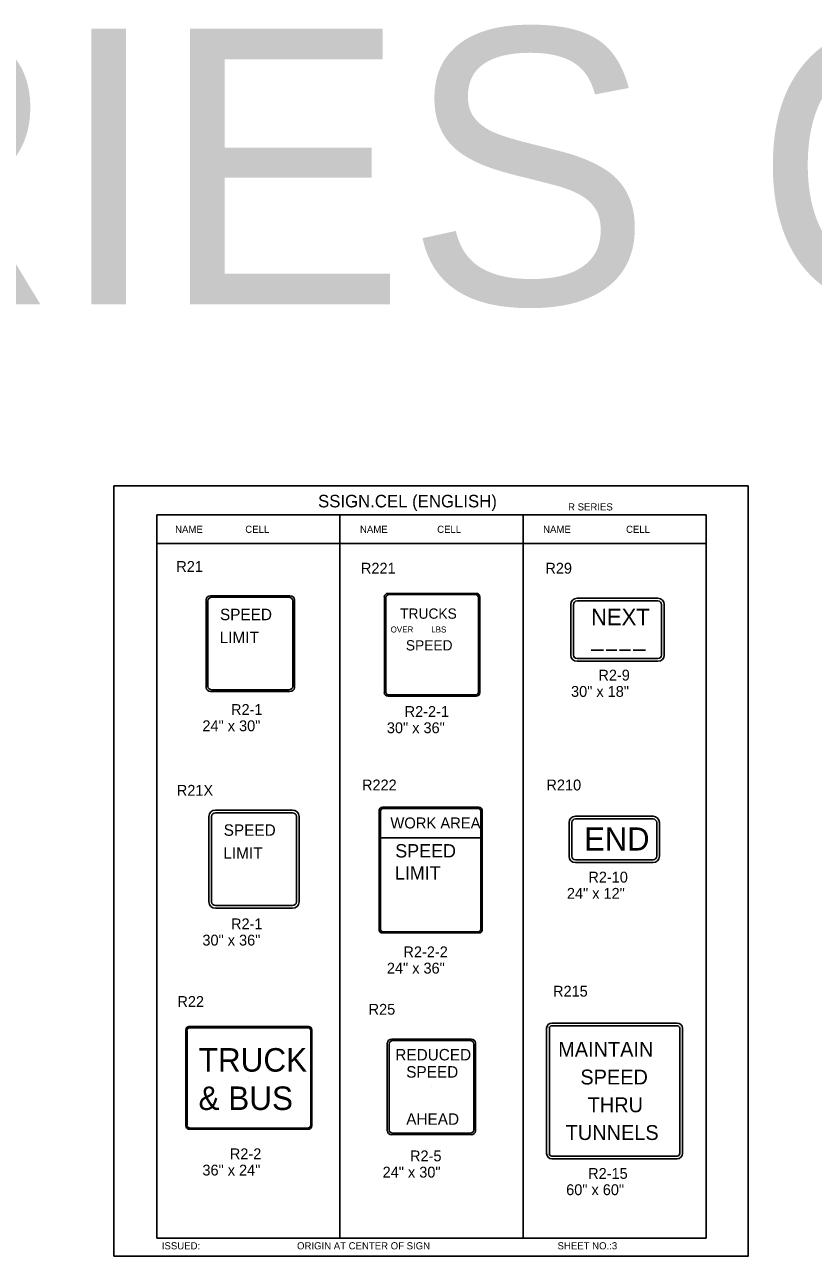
# Model space of a CAD drawing. Extents: x -5299 to 22597, y -19549 to -1808.
# Drawn here: x -3750 to -2878, y -3623 to -2261 of the extents above; entities that cross this region are included whole.
import ezdxf

# ---------------------------------------------------------------- set-up
doc = ezdxf.new("R2010")
doc.units = 0
for name, color, linetype in [('Level 1', 7, 'Continuous'), ('Level 2', 7, 'Continuous'), ('Level 3', 7, 'Continuous'), ('Level 63', 7, 'Continuous')]:
    doc.layers.add(name, color=color, linetype=linetype)

msp = doc.modelspace()

# ---------------------------------------------------------------- linework, layer by layer
at = {"layer": 'Level 1'}
for p, q in [((-2996.6, -2802.9), (-3603.6, -2802.9)), ((-3603.6, -2802.9), (-3603.6, -3602.9)), ((-3401.3, -2802.9), (-3401.3, -3602.9)), ((-3198.9, -2802.9), (-3198.9, -3602.9)), ((-2996.6, -2802.9), (-2996.6, -3602.9)), ((-2996.6, -2834.6), (-3603.6, -2834.6)), ((-3547.3, -2992.6), (-3547.3, -2897.9)), ((-3542.8, -2894), (-3457.9, -2894)), ((-3453.4, -2897.9), (-3453.4, -2992.6)), ((-3350.6, -2998.6), (-3350.6, -2894.6)), ((-3346.7, -2891.1), (-3252, -2891.1)), ((-3248.1, -2894.6), (-3248.1, -2998.6)), ((-3143.2, -2957.9), (-3143.2, -2902.1)), ((-3139.2, -2898.1), (-3049.7, -2898.1)), ((-3045.7, -2902.1), (-3045.7, -2957.9)), ((-3094.2, -2930.7), (-3094.2, -2930.7)), ((-3500.4, -2945.3), (-3500.4, -2945.3)), ((-3299.4, -2946.6), (-3299.4, -2946.6)), ((-3049.7, -2961.9), (-3139.2, -2961.9)), ((-3457.9, -2996.5), (-3542.8, -2996.5)), ((-3252, -3002.1), (-3346.7, -3002.1)), ((-3538.7, -3132.5), (-3453.9, -3132.5)), ((-3356.5, -3261.4), (-3356.5, -3130.4)), ((-3353, -3127.6), (-3249.1, -3127.6)), ((-3245.5, -3130.4), (-3245.5, -3261.4)), ((-3543.3, -3231.1), (-3543.3, -3136.4)), ((-3449.3, -3136.4), (-3449.3, -3231.1)), ((-3356.5, -3160), (-3245.5, -3160)), ((-3098.1, -3161.8), (-3098.1, -3161.8)), ((-3496.3, -3183.7), (-3496.3, -3183.7)), ((-3301, -3195.9), (-3301, -3195.9)), ((-3543.3, -3231.1), (-3543.3, -3231.1)), ((-3453.9, -3235), (-3538.7, -3235)), ((-3249.1, -3264.2), (-3353, -3264.2)), ((-3570.3, -3477.6), (-3570.3, -3373.7)), ((-3567.5, -3370.2), (-3436.5, -3370.2)), ((-3433.6, -3373.7), (-3433.6, -3477.6)), ((-3169.8, -3370.8), (-3169.8, -3509.5)), ((-3169.8, -3370.8), (-3169.8, -3370.8)), ((-3028.4, -3368), (-3167.1, -3368)), ((-3025.7, -3509.5), (-3025.7, -3370.8)), ((-3348.9, -3484.3), (-3348.9, -3387.1)), ((-3347, -3483), (-3347, -3388.3)), ((-3342.5, -3384.4), (-3257.7, -3384.4)), ((-3253.1, -3388.3), (-3253.1, -3483)), ((-3502, -3425.7), (-3502, -3425.7)), ((-3300.1, -3435.7), (-3300.1, -3435.7)), ((-3097.8, -3440.1), (-3097.8, -3440.1)), ((-3436.5, -3481.2), (-3567.5, -3481.2)), ((-3257.7, -3486.9), (-3342.5, -3486.9)), ((-3167.1, -3512.2), (-3028.4, -3512.2)), ((-3603.6, -3602.9), (-2996.6, -3602.9))]:
    msp.add_line(p, q, dxfattribs=at)
for centre, radius, start, end in [((-3139.2, -2902.1), 4, 90, 180), ((-3049.7, -2902.1), 4, 0, 90), ((-3139.2, -2957.9), 4, 180, 270), ((-3049.7, -2957.9), 4, 270, 0), ((-3167.1, -3370.8), 2.71, 90, 180), ((-3028.4, -3370.8), 2.71, 0, 90), ((-3167.1, -3509.5), 2.71, 180, 270), ((-3028.4, -3509.5), 2.71, 270, 0)]:
    msp.add_arc(centre, radius, start, end, dxfattribs=at)
for centre, major_axis, ratio, start_param, end_param in [((-3542.8, -2897.9), (-4.51, 0), 0.866667, 4.712389, 6.283185), ((-3457.9, -2897.9), (-4.51, 0), 0.866667, 3.141593, 4.712389), ((-3346.7, -2894.6), (-3.91, 0), 0.8975, 4.712389, 6.283185), ((-3252, -2894.6), (-3.91, 0), 0.8975, 3.141593, 4.712389), ((-3542.8, -2992.6), (4.51, 0), 0.866667, 3.141593, 4.712389), ((-3457.9, -2992.6), (4.51, 0), 0.866667, 4.712389, 6.283185), ((-3346.7, -2998.6), (3.91, 0), 0.8975, 3.141593, 4.712389), ((-3252, -2998.6), (3.91, 0), 0.8975, 4.712389, 6.283185), ((-3538.7, -3136.4), (-4.51, 0), 0.866667, 4.712389, 6.283185), ((-3453.9, -3136.4), (-4.51, 0), 0.866667, 3.141593, 4.712389), ((-3353, -3130.4), (-3.51, 0), 0.814228, 4.712389, 6.283185), ((-3249.1, -3130.4), (-3.51, 0), 0.814228, 3.141593, 4.712389), ((-3538.7, -3231.1), (4.51, 0), 0.866667, 3.141593, 4.712389), ((-3453.9, -3231.1), (4.51, 0), 0.866667, 4.712389, 6.283185), ((-3353, -3261.4), (3.51, 0), 0.814228, 3.141593, 4.712389), ((-3249.1, -3261.4), (3.51, 0), 0.814228, 4.712389, 6.283185), ((-3567.5, -3373.7), (0, -3.51), 0.814228, 3.141593, 4.712389), ((-3436.5, -3373.7), (0, 3.51), 0.814228, 4.712389, 6.283185), ((-3342.5, -3388.3), (-4.51, 0), 0.866667, 4.712389, 6.283185), ((-3257.7, -3388.3), (-4.51, 0), 0.866667, 3.141593, 4.712389), ((-3567.5, -3477.6), (0, -3.51), 0.814228, 4.712389, 6.283185), ((-3436.5, -3477.6), (0, 3.51), 0.814228, 3.141593, 4.712389), ((-3342.5, -3483), (4.51, 0), 0.866667, 3.141593, 4.712389), ((-3257.7, -3483), (4.51, 0), 0.866667, 4.712389, 6.283185)]:
    msp.add_ellipse(centre, major_axis=major_axis, ratio=ratio, start_param=start_param, end_param=end_param, dxfattribs=at)
at = {"layer": 'Level 3'}
for p, q in [((-3549.1, -2993.9), (-3549.1, -2896.7)), ((-3544.3, -2892.4), (-3456.5, -2892.4)), ((-3451.6, -2896.7), (-3451.6, -2993.9)), ((-3352.2, -2893.5), (-3352.2, -2999.7)), ((-3250.8, -2889.7), (-3348, -2889.7)), ((-3246.6, -2999.7), (-3246.6, -2893.5)), ((-3146.2, -2957.9), (-3146.2, -2902.1)), ((-3139.2, -2895.1), (-3049.7, -2895.1)), ((-3042.7, -2902.1), (-3042.7, -2957.9)), ((-3123.6, -2952.5), (-3110.1, -2952.5)), ((-3107.1, -2952.5), (-3095.1, -2952.5)), ((-3092.1, -2952.5), (-3080.1, -2952.5)), ((-3077.1, -2952.5), (-3063.6, -2952.5)), ((-3049.7, -2964.9), (-3139.2, -2964.9)), ((-3456.5, -2998.1), (-3544.3, -2998.1)), ((-3348, -3003.5), (-3250.8, -3003.5)), ((-3538.7, -3129.5), (-3453.9, -3129.5)), ((-3357.9, -3129.5), (-3357.9, -3262.3)), ((-3247.9, -3126.4), (-3354.1, -3126.4)), ((-3244.1, -3262.3), (-3244.1, -3129.5)), ((-3546.3, -3231.1), (-3546.3, -3136.4)), ((-3446.3, -3136.4), (-3446.3, -3231.1)), ((-3148, -3180.5), (-3148, -3143.3)), ((-3145, -3180.5), (-3145, -3143.3)), ((-3141, -3136.3), (-3055.1, -3136.3)), ((-3141, -3139.3), (-3055.1, -3139.3)), ((-3051.1, -3143.3), (-3051.1, -3180.5)), ((-3048.1, -3143.3), (-3048.1, -3180.5)), ((-3055.1, -3184.5), (-3141, -3184.5)), ((-3055.1, -3187.5), (-3141, -3187.5)), ((-3546.3, -3231.1), (-3546.3, -3231.1)), ((-3453.9, -3238), (-3538.7, -3238)), ((-3354.1, -3265.4), (-3247.9, -3265.4)), ((-3167.1, -3365), (-3028.4, -3365)), ((-3571.5, -3372.6), (-3571.5, -3478.8)), ((-3435.6, -3368.8), (-3568.4, -3368.8)), ((-3432.5, -3478.8), (-3432.5, -3372.6)), ((-3172.8, -3509.5), (-3172.8, -3370.8)), ((-3022.7, -3370.8), (-3022.7, -3509.5)), ((-3348.9, -3387.1), (-3348.9, -3484.3)), ((-3256.2, -3382.8), (-3344, -3382.8)), ((-3251.3, -3484.3), (-3251.3, -3387.1)), ((-3568.4, -3482.6), (-3435.6, -3482.6)), ((-3344, -3488.5), (-3256.2, -3488.5)), ((-3172.8, -3509.5), (-3172.8, -3509.5)), ((-3028.4, -3515.2), (-3167.1, -3515.2))]:
    msp.add_line(p, q, dxfattribs=at)
for centre, radius, start, end in [((-3139.2, -2902.1), 7, 90, 180), ((-3049.7, -2902.1), 7, 0, 90), ((-3139.2, -2957.9), 7, 180, 270), ((-3049.7, -2957.9), 7, 270, 0), ((-3141, -3143.3), 7, 90, 180), ((-3141, -3143.3), 4, 90, 180), ((-3055.1, -3143.3), 7, 0, 90), ((-3055.1, -3143.3), 4, 0, 90), ((-3141, -3180.5), 7, 180, 270), ((-3141, -3180.5), 4, 180, 270), ((-3055.1, -3180.5), 4, 270, 0), ((-3055.1, -3180.5), 7, 270, 0), ((-3167.1, -3370.8), 5.71, 90, 180), ((-3028.4, -3370.8), 5.71, 0, 90), ((-3167.1, -3509.5), 5.71, 180, 270), ((-3028.4, -3509.5), 5.71, 270, 0)]:
    msp.add_arc(centre, radius, start, end, dxfattribs=at)
for centre, major_axis, ratio, start_param, end_param in [((-3544.3, -2896.7), (-4.88, 0), 0.866667, 4.712389, 6.283185), ((-3456.5, -2896.7), (-4.88, 0), 0.866667, 3.141593, 4.712389), ((-3348, -2893.5), (-4.23, 0), 0.8975, 4.712389, 6.283185), ((-3250.8, -2893.5), (-4.23, 0), 0.8975, 3.141593, 4.712389), ((-3544.3, -2993.9), (4.88, 0), 0.866667, 3.141593, 4.712389), ((-3456.5, -2993.9), (4.88, 0), 0.866667, 4.712389, 6.283185), ((-3348, -2999.7), (4.23, 0), 0.8975, 3.141593, 4.712389), ((-3250.8, -2999.7), (4.23, 0), 0.8975, 4.712389, 6.283185), ((-3538.7, -3136.4), (-7.51, 0), 0.919923, 4.712389, 6.283185), ((-3453.9, -3136.4), (-7.51, 0), 0.919923, 3.141593, 4.712389), ((-3354.1, -3129.5), (-3.79, 0), 0.814228, 4.712389, 6.283185), ((-3247.9, -3129.5), (-3.79, 0), 0.814228, 3.141593, 4.712389), ((-3538.7, -3231.1), (7.51, 0), 0.919923, 3.141593, 4.712389), ((-3453.9, -3231.1), (7.51, 0), 0.919923, 4.712389, 6.283185), ((-3354.1, -3262.3), (3.79, 0), 0.814228, 3.141593, 4.712389), ((-3247.9, -3262.3), (3.79, 0), 0.814228, 4.712389, 6.283185), ((-3568.4, -3372.6), (0, -3.79), 0.814228, 3.141593, 4.712389), ((-3435.6, -3372.6), (0, 3.79), 0.814228, 4.712389, 6.283185), ((-3344, -3387.1), (-4.88, 0), 0.866667, 4.712389, 6.283185), ((-3344, -3387.1), (-4.88, 0), 0.866667, 4.712389, 6.283185), ((-3256.2, -3387.1), (-4.88, 0), 0.866667, 3.141593, 4.712389), ((-3568.4, -3478.8), (0, -3.79), 0.814228, 4.712389, 6.283185), ((-3435.6, -3478.8), (0, 3.79), 0.814228, 3.141593, 4.712389), ((-3344, -3484.3), (4.88, 0), 0.866667, 3.141593, 4.712389), ((-3256.2, -3484.3), (4.88, 0), 0.866667, 4.712389, 6.283185)]:
    msp.add_ellipse(centre, major_axis=major_axis, ratio=ratio, start_param=start_param, end_param=end_param, dxfattribs=at)
at = {"layer": 'Level 63'}
msp.add_lwpolyline([(-3651.1, -3623.1), (-2950.1, -3623.1), (-2950.1, -2770.8), (-3651.1, -2770.8)], close=True, dxfattribs=at)

# ---------------------------------------------------------------- texts
at = {"layer": 'Level 1'}
for s, height, p in [('SPEED', 12.68, (-3533.9, -2919.4)), ('TRUCKS', 11.38, (-3334.7, -2917.8)), ('OVER        LBS', 6.638, (-3345.3, -2933)), ('LIMIT', 12.68, (-3534.2, -2944.8)), ('SPEED', 11.38, (-3328.4, -2952.9)), ('SPEED', 12.68, (-3529.8, -3157.9)), ('WORK AREA', 12.19, (-3345.5, -3149.8)), ('END', 25.6, (-3131.3, -3174.2)), ('LIMIT', 12.68, (-3530.1, -3183.3)), ('SPEED', 14.79, (-3340.1, -3181.9)), ('LIMIT', 14.79, (-3340.5, -3206.4)), ('TRUCK', 26.01, (-3557.4, -3418.8)), ('MAINTAIN', 16.46, (-3160, -3402.3)), ('REDUCED', 12.68, (-3340.1, -3406.4)), ('SPEED', 12.68, (-3328, -3425.4)), ('SPEED', 16.46, (-3135.5, -3433)), ('& BUS', 26.01, (-3557.6, -3461.2)), ('THRU', 16.46, (-3127.4, -3463.7)), ('AHEAD', 12.68, (-3328, -3477.6)), ('TUNNELS', 16.46, (-3151.7, -3494.4))]:
    msp.add_text(s, height=height, dxfattribs=at).set_placement(p)
at = {"layer": 'Level 2'}
for s, p in [('R21', (-3582.2, -2866)), ('R221', (-3378.1, -2867.9)), ('R29', (-3174.2, -2867.9)), ('R21X', (-3581.6, -3113.6)), ('R222', (-3376.9, -3107.7)), ('R210', (-3173, -3107.7)), ('R215', (-3165.7, -3335.8)), ('R22', (-3581, -3347.2)), ('R25', (-3369.6, -3355.8))]:
    msp.add_text(s, height=12, dxfattribs=at).set_placement(p)
at = {"layer": 'Level 3'}
for s, height, p in [('R-SERIES CELLS', 304.775, (-4981.6, -2569.9)), ('SSIGN.CEL (ENGLISH)', 13.857, (-3425.5, -2794.6)), ('R SERIES', 7.92, (-3149.1, -2798)), ('NAME', 7.92, (-3583.5, -2822.8)), ('CELL', 7.92, (-3505.9, -2822.8)), ('NAME', 7.92, (-3379.1, -2822.8)), ('CELL', 7.92, (-3293.8, -2822.8)), ('NAME', 7.92, (-3176.7, -2822.8)), ('CELL', 7.92, (-3085, -2822.8)), ('NEXT', 18.21, (-3123.7, -2924.9)), ('R2-9', 12, (-3115.6, -2986.2)), ('30" x 18"', 12, (-3145.8, -3004.2)), ('R2-1', 12, (-3521.7, -3024.2)), ('R2-2-1', 12, (-3329.8, -3026.4)), ('24" x 30"', 12, (-3553.3, -3042.2)), ('30" x 36"', 12, (-3349.4, -3044.4)), ('R2-10', 12, (-3126.7, -3209.6)), ('24" x 12"', 12, (-3150.4, -3227.6)), ('R2-1', 12, (-3521.7, -3261.3)), ('30" x 36"', 12, (-3553.3, -3279.3)), ('R2-2-2', 12, (-3331.1, -3292.3)), ('24" x 36"', 12, (-3349.4, -3310.3)), ('R2-2', 12, (-3523, -3515.7)), ('R2-5', 12, (-3323.8, -3518)), ('36" x 24"', 12, (-3553.3, -3533.7)), ('24" x 30"', 12, (-3354.1, -3536)), ('R2-15', 12, (-3126.9, -3537.4)), ('60" x 60"', 12, (-3151.2, -3555.4)), ('ISSUED:', 7.92, (-3598.2, -3615.4)), ('ORIGIN AT CENTER OF SIGN', 7.918, (-3448.7, -3615.4)), ('SHEET NO.:3', 7.918, (-3160.7, -3615.4))]:
    msp.add_text(s, height=height, dxfattribs=at).set_placement(p)

doc.saveas('drawing.dxf')
